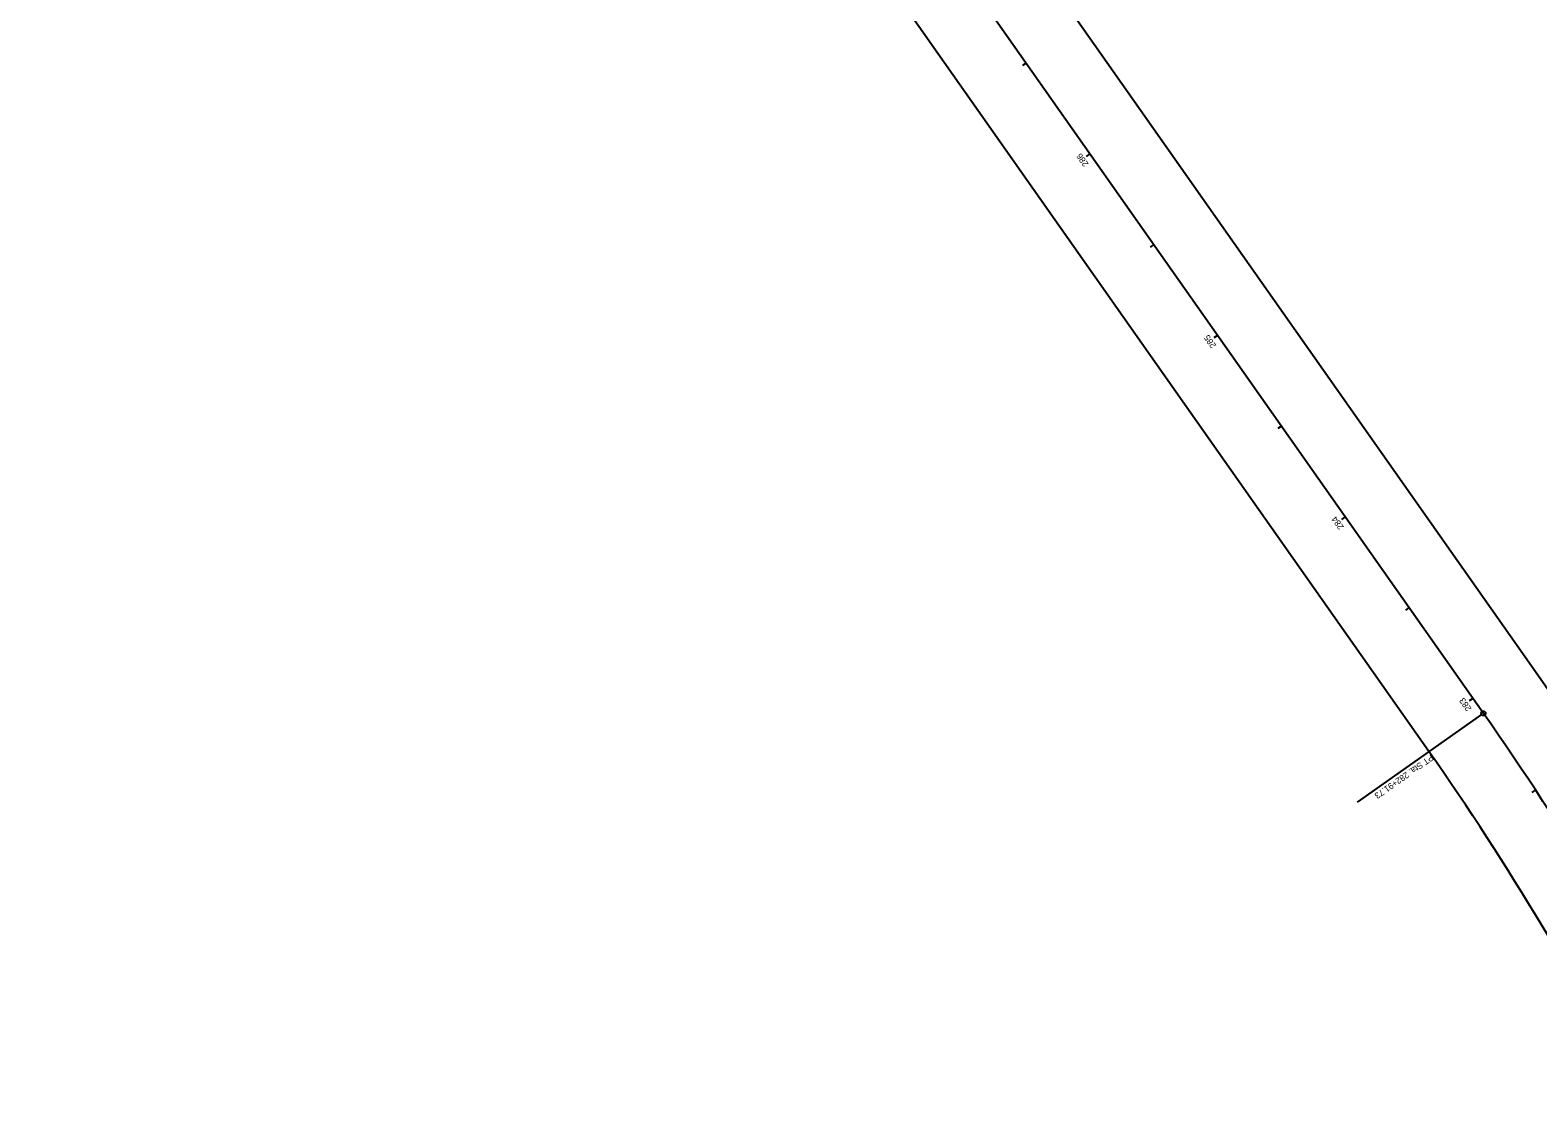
# Model space of a CAD drawing. Extents: x 1345023 to 1351589, y 535029 to 544731.
# Drawn here: x 1348802 to 1349481, y 538705 to 539191 of the extents above; entities that cross this region are included whole.
import ezdxf

# ---------------------------------------------------------------- set-up
doc = ezdxf.new("R2010")
doc.units = 0
for name, color, linetype in [('GE_X_CL_20', 7, 'Continuous'), ('RW_X_CL_20', 7, 'Continuous'), ('RW_X_Esmt_SH', 7, 'Continuous'), ('SV_X_Shot_Marker', 7, 'Continuous'), ('SV_X_Text_Elevation', 7, 'Continuous'), ('SV_X_Text_Name', 7, 'Continuous')]:
    doc.layers.add(name, color=color, linetype=linetype)

msp = doc.modelspace()

# ---------------------------------------------------------------- linework, layer by layer
at = {"layer": 'GE_X_CL_20'}
for p, q in [((1349250.45, 539176.2), (1349248.81, 539175.05)), ((1349279.21, 539135.3), (1349277.57, 539134.15)), ((1349307.97, 539094.4), (1349306.33, 539093.25)), ((1349336.73, 539053.5), (1349335.1, 539052.35)), ((1349365.5, 539012.6), (1349363.86, 539011.45)), ((1349394.26, 538971.7), (1349392.62, 538970.55)), ((1349423.02, 538930.81), (1349421.38, 538929.65)), ((1349451.78, 538889.91), (1349450.15, 538888.76)), ((1349455.72, 538882.57), (1349399.64, 538843.13)), ((1349479.99, 538848.63), (1349478.32, 538847.53))]:
    msp.add_line(p, q, dxfattribs=at)
msp.add_circle((1349456.54, 538883.15), 1, dxfattribs=at)
at = {"layer": 'RW_X_CL_20'}
msp.add_line((1349456.54, 538883.15), (1348162.36, 540723.41), dxfattribs=at)
msp.add_line((1349456.54, 538883.15), (1348162.36, 540723.41), dxfattribs=at)
msp.add_arc((1348395.69, 538137.11), 1296.91, 26.6506, 35.11662, dxfattribs=at)
msp.add_arc((1348395.69, 538137.11), 1296.91, 26.6506, 35.11662, dxfattribs=at)
at = {"layer": 'RW_X_Esmt_SH'}
for p, q in [((1349481.08, 538900.4), (1348186.89, 540740.69)), ((1349432, 538865.89), (1348137.84, 540706.13))]:
    msp.add_line(p, q, dxfattribs=at)
for radius, start in [(1326.91, 26.6506), (1266.91, 26.65061)]:
    msp.add_arc((1348395.69, 538137.11), radius, start, 35.11662, dxfattribs=at)
at = {"layer": 'SV_X_Shot_Marker'}
for p, q in [((1349456.5, 538883.11), (1349456.57, 538883.18)), ((1349456.5, 538883.18), (1349456.57, 538883.11))]:
    msp.add_line(p, q, dxfattribs=at)

# ---------------------------------------------------------------- texts
at = {"layer": 'GE_X_CL_20'}
for s, rotation, p in [('286', 125.11694, (1349278.76, 539130.73)), ('285', 125.11694, (1349336.28, 539048.94)), ('284', 125.11694, (1349393.78, 538967.17)), ('283', 125.11694, (1349451.33, 538885.33)), ('PT Sta. 282+91.73', 215.11662, (1349432.8, 538864.74))]:
    msp.add_text(s, height=2.8, rotation=rotation, dxfattribs=at).set_placement(p)
at = {"layer": 'SV_X_Text_Elevation'}
msp.add_text('0.00', height=0.06, dxfattribs=at).set_placement((1349456.34, 538883.09))
at = {"layer": 'SV_X_Text_Name'}
msp.add_text('EXCL275', height=0.06, dxfattribs=at).set_placement((1349456.19, 538883.15))

doc.saveas('drawing.dxf')
